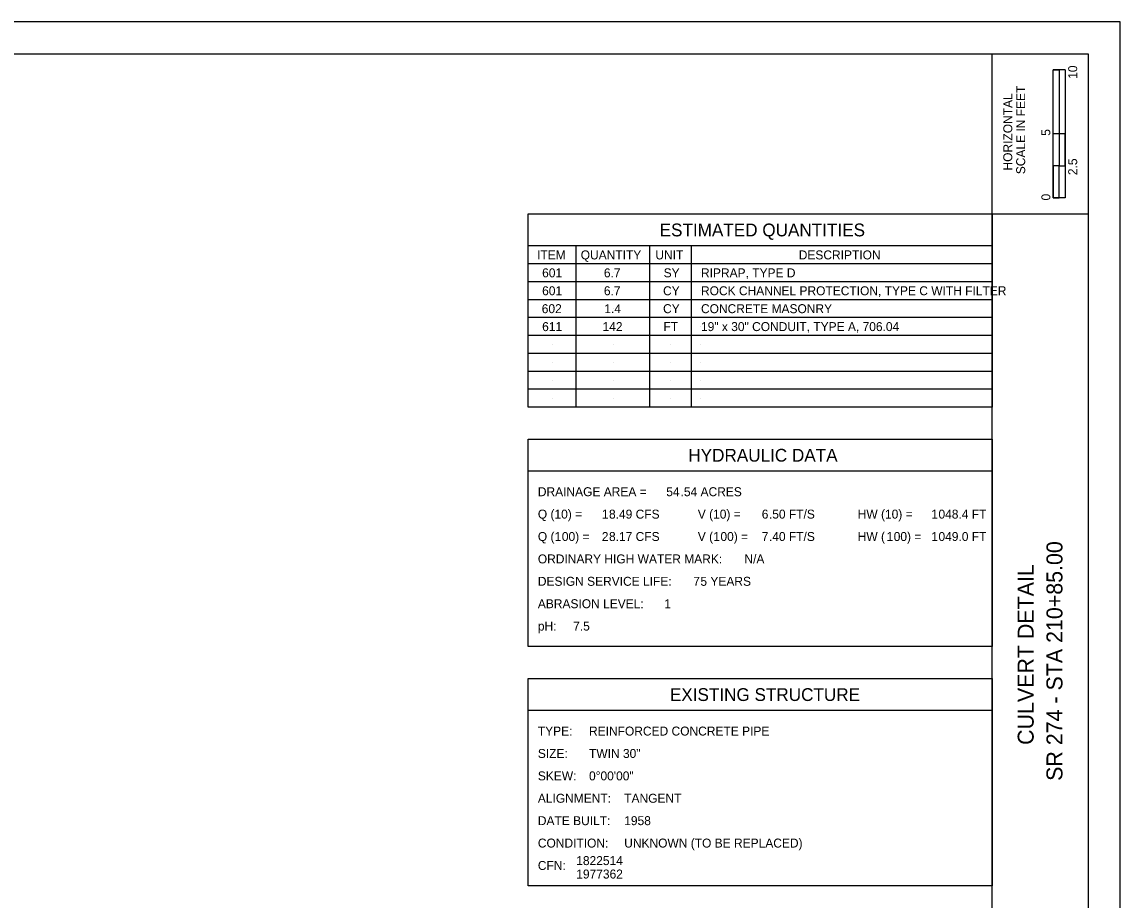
# Model space of a CAD drawing. Extents: x -0.3 to 34, y 0 to 22.
# Drawn here: x 16.84 to 34, y 8.28 to 22 of the extents above; entities that cross this region are included whole.
import ezdxf

# ---------------------------------------------------------------- set-up
doc = ezdxf.new("R2010")
doc.units = 0
for name, color, linetype in [('DT_X_Break_Line', 7, 'Continuous'), ('DT_X_Island', 7, 'Continuous'), ('DT_X_Void', 7, 'Continuous')]:
    doc.layers.add(name, color=color, linetype=linetype)

msp = doc.modelspace()

# ---------------------------------------------------------------- linework, layer by layer
at = {"layer": 'DT_X_Break_Line'}
msp.add_lwpolyline([(0, 0), (34, 0), (34, 22), (0, 22)], close=True, dxfattribs=at)
at = {"layer": 'DT_X_Island'}
for p, q in [((32, 0.5), (32, 21.5)), ((32, 19), (33.5, 19))]:
    msp.add_line(p, q, dxfattribs=at)
msp.add_lwpolyline([(1.5, 21.5), (33.5, 21.5), (33.5, 0.5), (1.5, 0.5)], close=True, dxfattribs=at)
at = {"layer": 'DT_X_Void'}
for p, q in [((32.957, 19.25), (32.957, 21.25)), ((33.144, 21.25), (32.957, 21.25)), ((32.957, 20.25), (32.957, 21.25)), ((32.957, 21.25), (33.05, 21.25)), ((33.05, 21.25), (33.051, 21.25)), ((33.051, 21.25), (33.051, 20.25)), ((33.144, 21.25), (33.144, 19.25)), ((33.051, 20.25), (32.957, 20.25)), ((33.143, 20.25), (33.05, 20.25)), ((33.05, 20.25), (33.05, 19.75)), ((33.143, 19.75), (33.143, 20.25)), ((33.05, 19.75), (32.957, 19.75)), ((32.957, 19.75), (32.957, 19.25)), ((33.05, 19.25), (33.05, 19.75)), ((33.05, 19.75), (33.143, 19.75)), ((33.144, 19.25), (32.957, 19.25)), ((32.957, 19.25), (33.05, 19.25)), ((32, 18.5), (24.75, 18.5)), ((25.5, 15.98), (25.5, 18.5)), ((26.65, 15.98), (26.65, 18.5)), ((27.3, 15.98), (27.3, 18.5)), ((32, 18.22), (24.75, 18.22)), ((25.125, 18.08), (25.125, 18.08)), ((26.075, 18.08), (26.075, 18.08)), ((26.975, 18.08), (26.975, 18.08)), ((27.45, 18.08), (27.45, 18.08)), ((32, 17.94), (24.75, 17.94)), ((25.125, 17.8), (25.125, 17.8)), ((26.075, 17.8), (26.075, 17.8)), ((26.975, 17.8), (26.975, 17.8)), ((27.45, 17.8), (27.45, 17.8)), ((32, 17.66), (24.75, 17.66)), ((25.125, 17.52), (25.125, 17.52)), ((26.075, 17.52), (26.075, 17.52)), ((26.975, 17.52), (26.975, 17.52)), ((27.45, 17.52), (27.45, 17.52)), ((32, 17.38), (24.75, 17.38)), ((25.125, 17.24), (25.125, 17.24)), ((26.075, 17.24), (26.075, 17.24)), ((26.975, 17.24), (26.975, 17.24)), ((27.45, 17.24), (27.45, 17.24)), ((32, 17.1), (24.75, 17.1)), ((25.125, 16.96), (25.125, 16.96)), ((26.075, 16.96), (26.075, 16.96)), ((26.975, 16.96), (26.975, 16.96)), ((27.45, 16.96), (27.45, 16.96)), ((32, 16.82), (24.75, 16.82)), ((25.125, 16.68), (25.125, 16.68)), ((26.075, 16.68), (26.075, 16.68)), ((26.975, 16.68), (26.975, 16.68)), ((27.45, 16.68), (27.45, 16.68)), ((32, 16.54), (24.75, 16.54)), ((25.125, 16.4), (25.125, 16.4)), ((26.075, 16.4), (26.075, 16.4)), ((26.975, 16.4), (26.975, 16.4)), ((27.45, 16.4), (27.45, 16.4)), ((32, 16.26), (24.75, 16.26)), ((25.125, 16.12), (25.125, 16.12)), ((26.075, 16.12), (26.075, 16.12)), ((26.975, 16.12), (26.975, 16.12)), ((27.45, 16.12), (27.45, 16.12)), ((32, 14.98), (24.75, 14.98)), ((32, 11.24), (24.75, 11.24))]:
    msp.add_line(p, q, dxfattribs=at)
for points in [[(24.75, 19), (32, 19), (32, 15.98), (24.75, 15.98)], [(24.75, 15.48), (32, 15.48), (32, 12.24), (24.75, 12.24)], [(24.75, 11.74), (32, 11.74), (32, 8.5), (24.75, 8.5)]]:
    msp.add_lwpolyline(points, close=True, dxfattribs=at)

# ---------------------------------------------------------------- texts
for s, height, p in [('10', 0.14, (33.33, 21.112)), ('SCALE IN FEET', 0.14, (32.517, 19.621)), ('HORIZONTAL', 0.14, (32.315, 19.679)), ('5', 0.14, (32.91, 20.221)), ('2.5', 0.14, (33.33, 19.607)), ('0', 0.14, (32.91, 19.211)), ('SR 274 - STA 210+85.00', 0.25, (33.1, 10.142)), ('CULVERT DETAIL', 0.25, (32.65, 10.704))]:
    msp.add_text(s, height=height, rotation=90, dxfattribs=at).set_placement(p)
for s, height, p in [('ESTIMATED QUANTITIES', 0.2, (26.804, 18.65)), ('ITEM', 0.14, (24.888, 18.29)), ('QUANTITY', 0.14, (25.57, 18.29)), ('UNIT', 0.14, (26.737, 18.29)), ('DESCRIPTION', 0.14, (28.978, 18.29)), ('601', 0.14, (24.967, 18.01)), ('6.7', 0.14, (25.932, 18.01)), ('SY', 0.14, (26.866, 18.01)), ('RIPRAP, TYPE D', 0.14, (27.45, 18.01)), ('601', 0.14, (24.967, 17.73)), ('6.7', 0.14, (25.932, 17.73)), ('CY', 0.14, (26.857, 17.73)), ('ROCK CHANNEL PROTECTION, TYPE C WITH FILTER', 0.14, (27.45, 17.73)), ('602', 0.14, (24.961, 17.45)), ('1.4', 0.14, (25.939, 17.45)), ('CY', 0.14, (26.857, 17.45)), ('CONCRETE MASONRY', 0.14, (27.45, 17.45)), ('611', 0.14, (24.967, 17.17)), ('142', 0.14, (25.911, 17.17)), ('FT', 0.14, (26.863, 17.17)), ('19" x 30" CONDUIT, TYPE A, 706.04', 0.14, (27.45, 17.17)), ('HYDRAULIC DATA', 0.2, (27.252, 15.13)), ('DRAINAGE AREA =', 0.14, (24.9, 14.59)), ('54', 0.14, (26.907, 14.59)), ('.54 ACRES', 0.14, (27.131, 14.59)), ('Q (10) =', 0.14, (24.9, 14.24)), ('1', 0.14, (25.9, 14.24)), ('8.49 CFS', 0.14, (26.012, 14.24)), ('V (10) =', 0.14, (27.4, 14.24)), ('6', 0.14, (28.4, 14.24)), ('.50 FT/S', 0.14, (28.512, 14.24)), ('HW (10) =', 0.14, (29.9, 14.24)), ('1', 0.14, (31.05, 14.24)), ('048.4 FT', 0.14, (31.162, 14.24)), ('Q (', 0.14, (24.9, 13.89)), ('1', 0.14, (25.163, 13.89)), ('00) =', 0.14, (25.275, 13.89)), ('2', 0.14, (25.9, 13.89)), ('8.17 CFS', 0.14, (26.012, 13.89)), ('V (', 0.14, (27.4, 13.89)), ('1', 0.14, (27.642, 13.89)), ('00) =', 0.14, (27.754, 13.89)), ('7', 0.14, (28.4, 13.89)), ('.40 FT/S', 0.14, (28.512, 13.89)), ('HW (', 0.14, (29.9, 13.89)), ('1', 0.14, (30.35, 13.89)), ('00) =', 0.14, (30.462, 13.89)), ('1', 0.14, (31.05, 13.89)), ('049.0 FT', 0.14, (31.162, 13.89)), ('ORDINARY HIGH WATER MARK:', 0.14, (24.9, 13.54)), ('N/A', 0.14, (28.129, 13.54)), ('DESIGN SERVICE LIFE:', 0.14, (24.9, 13.19)), ('7', 0.14, (27.329, 13.19)), ('5 YEARS', 0.14, (27.441, 13.19)), ('ABRASION LEVEL:', 0.14, (24.9, 12.84)), ('1', 0.14, (26.876, 12.84)), ('pH:', 0.14, (24.9, 12.49)), ('7.5', 0.14, (25.452, 12.49)), ('EXISTING STRUCTURE', 0.2, (26.964, 11.39)), ('TYPE:', 0.14, (24.9, 10.85)), ('REINFORCED CONCRETE PIPE', 0.14, (25.7, 10.85)), ('SIZE:', 0.14, (24.9, 10.5)), ('TWIN 30"', 0.14, (25.7, 10.5)), ('SKEW:', 0.14, (24.9, 10.15)), ('0°00\'00"', 0.14, (25.7, 10.15)), ('ALIGNMENT:', 0.14, (24.9, 9.8)), ('TANGENT', 0.14, (26.25, 9.8)), ('DATE BUILT:', 0.14, (24.9, 9.45)), ('1958', 0.14, (26.25, 9.45)), ('CONDITION:', 0.14, (24.9, 9.1)), ('UNKNOWN (TO BE REPLACED)', 0.14, (26.25, 9.1)), ('1822514 ', 0.14, (25.5, 8.826)), ('CFN:', 0.14, (24.9, 8.75)), ('1977362', 0.14, (25.5, 8.616))]:
    msp.add_text(s, height=height, dxfattribs=at).set_placement(p)

doc.saveas('drawing.dxf')
